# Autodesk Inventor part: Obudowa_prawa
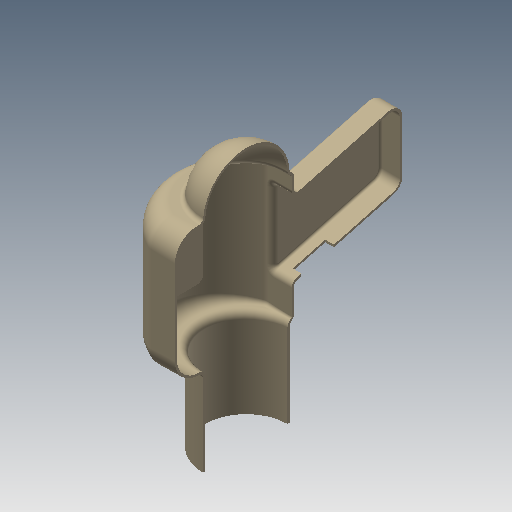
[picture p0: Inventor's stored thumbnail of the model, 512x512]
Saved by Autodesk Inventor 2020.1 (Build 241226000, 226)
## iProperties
Created: 2005-10
Part Number: Obudowa_prawa
Document SubType Name: Modeling
Designer: F.Stasiak
Density: 1 g/cm^3
Material: Ogólny
Appearance: Beżowa
Manager: www.cadconsulting.pl
Company: Fabian Stasiak CAD Consulting
Author: F.Stasiak
Subject: Zbiór ćwiczeń. Autodesk Inventor 2020. Kurs podstawowy
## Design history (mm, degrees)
sketch "Szkic2"
  geometry: L1 (11.99, 27.5)-(0, 27.5); L2 (0, 27.5)-(0, -27.5); L3 (0, -27.5)-(11.99, -27.5); A1 r 30 centre (0, 0) between (11.99, 27.5) and (11.99, -27.5); A2 r 30 centre (0, 0) between (11.99, -27.5) and (11.99, 27.5); 2 further points
  constraints: 6 end point, 4 point on circle, 2 centre point, 2 coincident, 2 concentric, 1 horizontal, 1 midpoint, 1 parallel, 1 perpendicular
  dimensions: "d0" = 60 diameter of A1; "d1" = 55 distance between parallel lines of L3 L1
extrude "Wyciągnięcie proste1" new body sketch "Szkic2" stored distance "d2" = 60; taper "d3" = 0 deg
sketch "Szkic3"
  geometry: L1 (0, 27.5)-(0, -27.5) reference; L2 (0, -25.5)-(0, 14.5); A1 r 20 centre (0, -5.5) between (0, -25.5) and (0, 14.5); A2 r 20 centre (0, -5.5) between (0, 14.5) and (0, -25.5)
  constraints: 4 point on circle, 3 point on line, 2 centre point, 2 concentric, 2 end point
  dimensions: "d4" = 40 diameter of A1; "d5" = 22 distance of L1.end A1.centre
extrude "Wyciągnięcie proste2" join sketch "Szkic3" distance "d6" = 40; taper "d7" = 0 deg
sketch "Szkic5"
  geometry: L1 (0, 27.5)-(0, -27.5) reference; L2 (0, -14.5)-(0, 25.5); A1 r 20 centre (0, 5.5) between (0, -14.5) and (0, 25.5); A2 r 20 centre (0, 5.5) between (0, 25.5) and (0, -14.5)
  constraints: 4 point on circle, 3 point on line, 2 centre point, 2 end point, 1 concentric
  dimensions: "d11" = 40 diameter of A1; "d41" = 22 distance of L1.start A1.centre
revolve "Obrót1" sketch "Szkic5" stored, may be unused: angle "d12" = 90 deg
sketch "Szkic6"
  geometry: L1 (55, 0)-(55, 60) reference; L2 (55, 50)-(105, 63.397); L3 (105, 63.397)-(105, 28.397); L4 (105, 28.397)-(55, 15); L5 (55, 15)-(55, 50)
  constraints: 8 end point, 2 parallel, 2 point on line, 1 collinear
  dimensions: "d13" = 35 distance of L2.end L3.end; "d14" = 75 deg angle of L3 L2; "d15" = 50 distance between parallel lines of L1 L3; "d16" = 15 distance of L1.start L4.end
extrude "Wyciągnięcie proste4" join sketch "Szkic6" distance "d17" = 10; taper "d18" = 0 deg
fillet "Zaokrąglenie1" dims "d19" = 5
fillet "Zaokrąglenie2" dims "d20" = 2
fillet "Zaokrąglenie3" dims "d21" = 2
fillet "Zaokrąglenie9" dims "d30" = 10, "d31" = 2, "d32" = 2, "d33" = 11
fillet "Zaokrąglenie10" dims "d34" = 2
node "Płaszczyzna konstrukcyjna1"
node "Płaszczyzna konstrukcyjna2"
node "Płaszczyzna konstrukcyjna3"
sketch "Szkic7"
  geometry: L1 (16.533, 11.401)-(-18.467, 11.401); L2 (-18.467, 11.401)-(-18.467, -10.599); L3 (-18.467, -10.599)-(16.533, -10.599); L4 (16.533, -10.599)-(16.533, 11.401)
  constraints: 8 end point, 2 parallel, 1 horizontal, 1 perpendicular
  dimensions: "d35" = 35 distance of L2.end L3.end; "d36" = 22 distance of L3.end L1.start
extrude "Wyciągnięcie proste5" cut sketch "Szkic7" distance "d37" = 3; taper "d38" = 0 deg
fillet "Zaokrąglenie11" dims "d39" = 2
sketch "SZKIC POD 4 OTWORY"
  geometry: L1 (22, 20)-(-22, 20); L2 (-22, 20)-(-22, -20); L3 (-22, -20)-(22, -20); L4 (22, -20)-(22, 20); L5 (0, 20)-(0, -20); 6 further points
  constraints: 10 end point, 5 coincident, 3 midpoint, 2 parallel, 1 horizontal, 1 perpendicular
  dimensions: "d49" = 44 distance of L2.end L3.end; "d50" = 40 distance of L1.end L2.end
sketch "SZKIC POD 2 OTWORY"
  geometry: L1 (-97, 53.881)-(-97, 33.881); L2 (-105, 56.881)-(-105, 32.234) reference; A1 r 5 centre (-100, 56.881) between (-98.706, 61.711) and (-105, 56.881) reference
  constraints: 2 end point, 1 vertical
  dimensions: "d51" = 20 distance of L1.start L1.end; "d52" = 8 distance between parallel lines of L1 L2; "d53" = 3 horizontal distance of A1.centre L1.start
feature "Skorupa1" dims "d40" = 1
sketch "Szkic8"
  geometry: L1 (0, -73.794)-(0, -28.982) reference; L2 (0, -30.982)-(4, -30.982); L3 (4, -30.982)-(4, -45.982); L4 (4, -45.982)-(0, -45.982); L5 (0, -45.982)-(0, -30.982)
  constraints: 8 end point, 2 parallel, 1 collinear, 1 horizontal, 1 perpendicular
  dimensions: "d43" = 15 distance of L2.end L3.end; "d44" = 4 distance of L3.end L4.end; "d45" = 2 distance from line of L1.end L2
extrude "Wyciągnięcie proste6" cut sketch "Szkic8" stored distance "d46" = 10; taper "d47" = 0 deg
node "Bryła1"
node "Korpusy bryłowe"
node "Korpusy powierzchniowe"
